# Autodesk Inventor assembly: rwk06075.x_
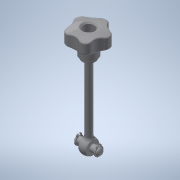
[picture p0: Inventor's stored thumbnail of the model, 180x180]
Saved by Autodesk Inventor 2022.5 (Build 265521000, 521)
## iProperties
Part Number: rwk06075.x_
Material: 一般
Document SubType Name: Assembly
Designer: ImaoCorp
Sending System: SOLIDWORKS 2017-2017317
MC: AMD64
MC_MODEL: Intel64 Family 6 Model 60 Stepping 3, GenuineIntel
OS: Windows_NT
FRU: Parasolid Version 29.0, build 201,  4-17-2017
FORMAT: text
GUISE: transmit
KEY: rwk06075
FILE: rwk06075.x_t
DATE: Wed Sep 04 15:56:46 2019
Author: ImaoCorp
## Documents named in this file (3)
- X:\14_SW2022-Inv2022\00_全2023-1023新製品(TCC)まで\r\rwk06075\RWK06075.iam
- X:\14_SW2022-Inv2022\00_全2023-1023新製品(TCC)まで\r\rwk06075\rwk06075_01.ipt
- X:\14_SW2022-Inv2022\00_全2023-1023新製品(TCC)まで\r\rwk06075\rwk06075_02.ipt
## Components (2 placed, 2 different names)
1. rwk06075_01
2. rwk06075_02
